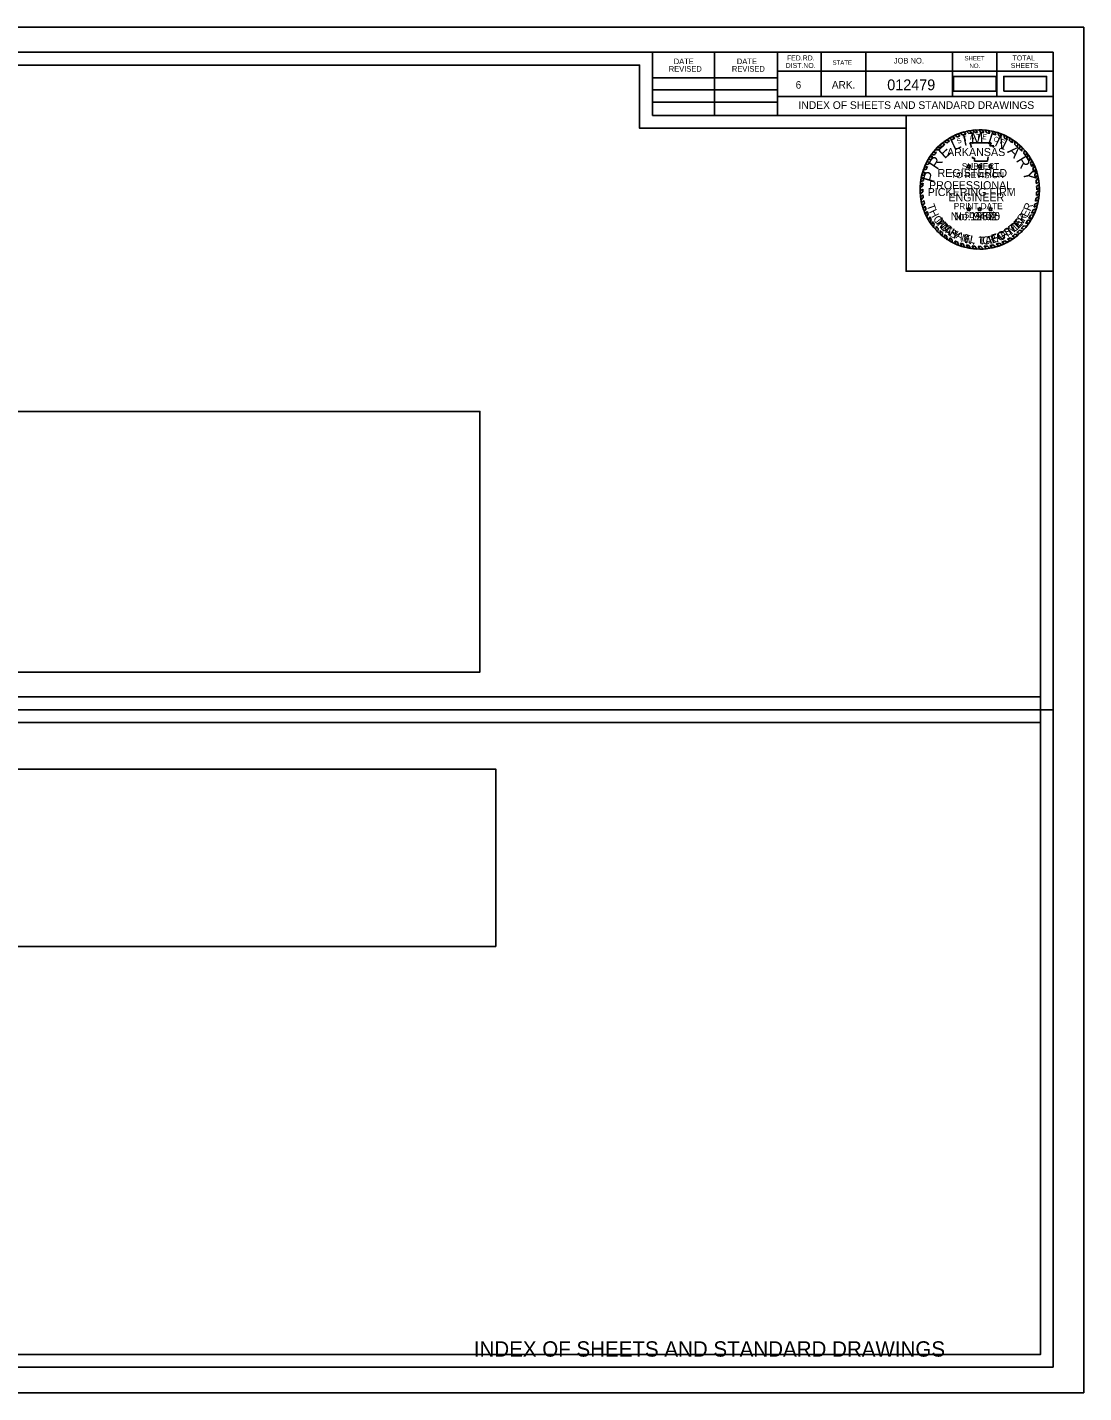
# Model space of a CAD drawing. Extents: x 1369290 to 1369980, y 379348 to 379562.
# Drawn here: x 1369458.1 to 1369623.1, y 379348.4 to 379561.7 of the extents above; entities that cross this region are included whole.
import ezdxf

# ---------------------------------------------------------------- set-up
doc = ezdxf.new("R2010")
doc.units = 0
for name, color, linetype in [('Default', 7, 'Continuous'), ('R_Border', 7, 'Continuous'), ('R_Border Notes', 7, 'Continuous'), ('R_Border Plan-Plan', 7, 'Continuous'), ('R_Border Title', 7, 'Continuous'), ('R_No Plot', 7, 'Continuous'), ('STAMP_PE_CRAFTON', 7, 'Continuous'), ('STAMP_PE_FOSTER', 7, 'Continuous'), ('STAMP_PE_SEAL-INFO', 7, 'Continuous'), ('STAMP_PE_TAEGTMEYER', 7, 'Continuous'), ('STAMP_PE_TXT', 7, 'Continuous'), ('STAMP_PRELIMINARY', 7, 'Continuous')]:
    doc.layers.add(name, color=color, linetype=linetype)

msp = doc.modelspace()

# ---------------------------------------------------------------- linework, layer by layer
at = {"layer": 'Default'}
for points in [[(1369602.79, 379551.74), (1369609.47, 379551.74), (1369609.47, 379554.05), (1369602.79, 379554.05)], [(1369610.66, 379551.74), (1369617.34, 379551.74), (1369617.34, 379554.05), (1369610.66, 379554.05)], [(1369384.17, 379460.99), (1369528.79, 379460.99), (1369528.79, 379501.71), (1369384.17, 379501.71)], [(1369381.68, 379418.12), (1369531.28, 379418.12), (1369531.28, 379445.83), (1369381.68, 379445.83)]]:
    msp.add_lwpolyline(points, close=True, dxfattribs=at)
at = {"layer": 'R_Border'}
for p, q in [((1369302.22, 379557.83), (1369618.4, 379557.83)), ((1369555.76, 379547.95), (1369555.76, 379557.83)), ((1369565.44, 379547.95), (1369565.44, 379557.83)), ((1369575.3, 379557.83), (1369575.3, 379547.95)), ((1369582.14, 379557.83), (1369582.14, 379550.89)), ((1369589.08, 379557.83), (1369589.08, 379550.89)), ((1369602.66, 379557.83), (1369602.66, 379550.89)), ((1369609.6, 379557.83), (1369609.6, 379550.89)), ((1369618.4, 379352.37), (1369618.4, 379557.83)), ((1369555.76, 379553.81), (1369575.3, 379553.81)), ((1369618.4, 379554.89), (1369575.3, 379554.89)), ((1369618.4, 379554.91), (1369618.4, 379554.91)), ((1369555.76, 379551.95), (1369575.3, 379551.95)), ((1369555.76, 379550.01), (1369575.3, 379550.01)), ((1369618.4, 379550.89), (1369575.3, 379550.89)), ((1369578.26, 379550.89), (1369618.4, 379550.89)), ((1369618.4, 379547.95), (1369555.76, 379547.95)), ((1369618.4, 379352.37), (1369302.22, 379352.37))]:
    msp.add_line(p, q, dxfattribs=at)
at = {"layer": 'R_Border Plan-Plan'}
msp.add_line((1369302.22, 379455.1), (1369618.4, 379455.1), dxfattribs=at)
at = {"layer": 'R_No Plot'}
for points in [[(1369289.81, 379561.73), (1369623.15, 379561.73), (1369623.15, 379348.39), (1369289.81, 379348.39)], [(1369616.4, 379457.1), (1369304.22, 379457.1), (1369304.22, 379555.83), (1369553.76, 379555.83), (1369553.76, 379545.95), (1369571.3, 379545.95), (1369595.4, 379545.95), (1369595.4, 379523.62), (1369616.4, 379523.62)], [(1369304.22, 379555.83), (1369553.76, 379555.83), (1369553.76, 379545.95), (1369571.3, 379545.95), (1369595.4, 379545.95), (1369595.4, 379523.62), (1369616.4, 379523.62), (1369616.4, 379354.37), (1369304.22, 379354.37)], [(1369595.4, 379547.95), (1369618.4, 379547.95), (1369618.4, 379523.62), (1369595.4, 379523.62)], [(1369304.22, 379453.1), (1369616.4, 379453.1), (1369616.4, 379354.37), (1369304.22, 379354.37)]]:
    msp.add_lwpolyline(points, close=True, dxfattribs=at)
at = {"layer": 'STAMP_PE_SEAL-INFO'}
for p, q in [((1369603, 379544.86), (1369603.39, 379544.59)), ((1369603.51, 379545.08), (1369603.8, 379544.75)), ((1369603.86, 379545.21), (1369604.24, 379544.9)), ((1369604.45, 379545.39), (1369604.74, 379545.04)), ((1369604.83, 379545.49), (1369605.19, 379545.14)), ((1369605.32, 379545.58), (1369605.62, 379545.22)), ((1369605.83, 379545.66), (1369606.11, 379545.27)), ((1369606.57, 379545.3), (1369606.26, 379545.7)), ((1369607.07, 379545.31), (1369606.79, 379545.72)), ((1369607.52, 379545.29), (1369607.27, 379545.71)), ((1369608.03, 379545.24), (1369607.74, 379545.68)), ((1369608.46, 379545.17), (1369608.2, 379545.63)), ((1369609.02, 379545.05), (1369608.84, 379545.51)), ((1369609.42, 379544.94), (1369609.26, 379545.41)), ((1369609.87, 379544.8), (1369609.73, 379545.28)), ((1369610.29, 379544.64), (1369610.15, 379545.13)), ((1369610.75, 379544.43), (1369610.65, 379544.93)), ((1369611.2, 379544.2), (1369611.11, 379544.71)), ((1369599.94, 379542.6), (1369600.46, 379542.56)), ((1369600.26, 379542.94), (1369600.8, 379542.9)), ((1369600.59, 379543.26), (1369601.05, 379543.12)), ((1369600.94, 379543.56), (1369601.47, 379543.46)), ((1369601.31, 379543.89), (1369601.77, 379543.69)), ((1369601.73, 379544.16), (1369602.18, 379543.96)), ((1369602.12, 379544.4), (1369602.55, 379544.18)), ((1369602.57, 379544.65), (1369603.03, 379544.43)), ((1369605.37, 379543.69), (1369608.71, 379543.69)), ((1369605.49, 379543.38), (1369605.37, 379543.69)), ((1369605.59, 379543.08), (1369605.49, 379543.38)), ((1369605.6, 379542.97), (1369605.59, 379543.08)), ((1369608.71, 379543.69), (1369608.49, 379543.19)), ((1369608.49, 379543.19), (1369609.12, 379543.19)), ((1369609.12, 379543.19), (1369608.98, 379542.97)), ((1369611.58, 379543.98), (1369611.54, 379544.48)), ((1369612.02, 379543.69), (1369611.99, 379544.2)), ((1369612.38, 379543.42), (1369612.41, 379543.91)), ((1369612.83, 379543.05), (1369612.85, 379543.57)), ((1369613.14, 379542.76), (1369613.21, 379543.26)), ((1369613.5, 379542.38), (1369613.56, 379542.91)), ((1369613.77, 379542.07), (1369613.91, 379542.54)), ((1369598.6, 379540.65), (1369599.1, 379540.71)), ((1369598.83, 379541.07), (1369599.32, 379541.09)), ((1369599.08, 379541.47), (1369599.59, 379541.5)), ((1369599.31, 379541.82), (1369599.82, 379541.81)), ((1369599.59, 379542.18), (1369600.14, 379542.21)), ((1369605.79, 379541.26), (1369605.77, 379541.48)), ((1369606.11, 379541.26), (1369605.79, 379541.26)), ((1369606.11, 379540.83), (1369606.11, 379541.26)), ((1369608.14, 379540.83), (1369606.11, 379540.83)), ((1369608.15, 379541.17), (1369608.14, 379540.83)), ((1369608.23, 379541.48), (1369608.15, 379541.17)), ((1369614.1, 379541.65), (1369614.23, 379542.15)), ((1369614.32, 379541.34), (1369614.49, 379541.8)), ((1369614.62, 379540.84), (1369614.81, 379541.33)), ((1369614.82, 379540.47), (1369615.05, 379540.92)), ((1369615.05, 379539.99), (1369615.28, 379540.47)), ((1369598.18, 379538.26), (1369597.72, 379538.01)), ((1369597.82, 379538.51), (1369598.29, 379538.7)), ((1369597.92, 379538.92), (1369598.4, 379539.08)), ((1369598.08, 379539.42), (1369598.56, 379539.56)), ((1369598.23, 379539.83), (1369598.73, 379539.97)), ((1369598.41, 379540.26), (1369598.91, 379540.36)), ((1369615.19, 379539.65), (1369615.46, 379540.08)), ((1369615.39, 379539.1), (1369615.66, 379539.58)), ((1369615.5, 379538.74), (1369615.79, 379539.19)), ((1369615.63, 379538.18), (1369615.95, 379538.63)), ((1369598, 379536.94), (1369597.58, 379536.69)), ((1369597.98, 379536.45), (1369597.58, 379536.11)), ((1369598.04, 379537.37), (1369597.6, 379537.09)), ((1369598.1, 379537.8), (1369597.65, 379537.58)), ((1369615.7, 379537.8), (1369616.05, 379538.15)), ((1369615.77, 379537.29), (1369616.14, 379537.63)), ((1369615.8, 379536.87), (1369616.19, 379537.16)), ((1369615.8, 379535.95), (1369616.22, 379536.22)), ((1369615.81, 379536.35), (1369616.22, 379536.67)), ((1369597.99, 379536.04), (1369597.6, 379535.72)), ((1369598.02, 379535.55), (1369597.65, 379535.19)), ((1369598.08, 379535.12), (1369597.72, 379534.74)), ((1369598.15, 379534.66), (1369597.81, 379534.29)), ((1369598.25, 379534.24), (1369597.94, 379533.83)), ((1369615.51, 379534.1), (1369615.98, 379534.3)), ((1369615.62, 379534.55), (1369616.07, 379534.75)), ((1369615.71, 379535.05), (1369616.15, 379535.27)), ((1369615.76, 379535.44), (1369616.19, 379535.7)), ((1369598.37, 379533.79), (1369598.08, 379533.38)), ((1369598.51, 379533.37), (1369598.23, 379532.96)), ((1369598.68, 379532.94), (1369598.42, 379532.52)), ((1369598.85, 379532.56), (1369598.62, 379532.1)), ((1369599.08, 379532.1), (1369598.89, 379531.61)), ((1369614.58, 379531.88), (1369615.08, 379531.93)), ((1369614.85, 379532.38), (1369615.34, 379532.44)), ((1369615.01, 379532.71), (1369615.5, 379532.81)), ((1369615.23, 379533.23), (1369615.71, 379533.36)), ((1369615.36, 379533.61), (1369615.85, 379533.81)), ((1369599.32, 379531.7), (1369599.14, 379531.23)), ((1369599.52, 379531.39), (1369599.41, 379530.83)), ((1369599.8, 379531), (1369599.7, 379530.47)), ((1369600.11, 379530.62), (1369600.02, 379530.1)), ((1369600.41, 379530.28), (1369600.35, 379529.76)), ((1369600.73, 379529.96), (1369600.7, 379529.43)), ((1369613.12, 379530.02), (1369613.56, 379529.88)), ((1369613.38, 379530.28), (1369613.86, 379530.19)), ((1369613.76, 379530.71), (1369614.22, 379530.63)), ((1369614.07, 379531.1), (1369614.57, 379531.11)), ((1369614.41, 379531.6), (1369614.89, 379531.59)), ((1369601.08, 379529.64), (1369601.07, 379529.11)), ((1369601.44, 379529.35), (1369601.46, 379528.82)), ((1369601.78, 379529.1), (1369601.81, 379528.58)), ((1369602.2, 379528.82), (1369602.26, 379528.3)), ((1369602.55, 379528.61), (1369602.64, 379528.1)), ((1369603.03, 379528.36), (1369603.19, 379527.84)), ((1369603.41, 379528.19), (1369603.58, 379527.68)), ((1369603.9, 379528), (1369604.11, 379527.5)), ((1369604.31, 379527.87), (1369604.53, 379527.38)), ((1369604.82, 379527.73), (1369605.03, 379527.26)), ((1369605.21, 379527.64), (1369605.46, 379527.18)), ((1369608.5, 379527.63), (1369608.89, 379527.29)), ((1369608.99, 379527.73), (1369609.37, 379527.41)), ((1369609.45, 379527.85), (1369609.87, 379527.56)), ((1369609.94, 379528.02), (1369610.39, 379527.75)), ((1369610.36, 379528.18), (1369610.78, 379527.92)), ((1369610.82, 379528.39), (1369611.3, 379528.18)), ((1369611.23, 379528.6), (1369611.65, 379528.37)), ((1369611.64, 379528.85), (1369612.09, 379528.65)), ((1369611.99, 379529.08), (1369612.43, 379528.89)), ((1369612.45, 379529.42), (1369612.92, 379529.27)), ((1369612.72, 379529.64), (1369613.19, 379529.52)), ((1369605.71, 379527.56), (1369605.95, 379527.12)), ((1369606.15, 379527.51), (1369606.43, 379527.08)), ((1369606.64, 379527.48), (1369606.94, 379527.07)), ((1369607.1, 379527.48), (1369607.44, 379527.09)), ((1369607.61, 379527.51), (1369607.94, 379527.13)), ((1369608.05, 379527.56), (1369608.43, 379527.2))]:
    msp.add_line(p, q, dxfattribs=at)
for radius, start, end in [(9.32, 111.3124, 114.7026), (8.91, 110.3086, 113.1659), (9.32, 105.2339, 109.0352), (8.91, 104.0352, 107.3615), (9.32, 99.7525, 102.7765), (8.91, 98.258, 101.0329), (9.32, 93.9381, 96.5517), (8.91, 92.1102, 95.0367), (9.32, 87.7298, 90.6707), (8.91, 85.9628, 88.9097), (9.32, 81.9732, 84.8236), (8.91, 79.9264, 82.696), (9.32, 75.3125, 77.9426), (8.91, 73.5575, 76.2314), (9.32, 69.6061, 72.3058), (8.91, 67.6248, 70.504), (9.32, 63.1329, 66.2704), (9.32, 135.4021, 138.3031), (8.91, 133.1331, 136.2562), (9.32, 129.7326, 132.5376), (8.91, 127.5297, 130.9683), (9.32, 123.6199, 126.5906), (8.91, 121.9746, 125.11), (9.32, 117.6544, 120.8099), (8.91, 115.6869, 119.1583), (8.91, 61.1558, 64.3784), (9.32, 56.9003, 60.0942), (8.91, 54.9238, 58.2702), (8.91, 48.3016, 52.0395), (9.32, 50.3492, 53.7159), (8.91, 42.2212, 45.5512), (9.32, 44.3405, 47.3929), (9.32, 38.1247, 41.2316), (9.32, 152.864, 155.5189), (9.32, 147.0072, 149.899), (8.91, 151.0315, 153.573), (9.32, 141.6056, 144.4486), (8.91, 145.0197, 148.2104), (8.91, 139.301, 142.5873), (8.91, 36.135, 39.5311), (8.91, 29.9032, 33.6645), (9.32, 31.9614, 35.4294), (8.91, 23.7732, 27.2211), (9.32, 25.9391, 29.0125), (9.32, 164.3068, 166.894), (9.32, 158.4077, 161.0701), (8.91, 167.9048, 170.9039), (8.91, 162.4331, 165.0013), (8.91, 156.3402, 159.2319), (8.91, 17.6802, 21.4251), (9.32, 19.9538, 23.3141), (8.91, 11.5444, 15.2364), (9.32, 13.8421, 17.4447), (9.32, 175.7409, 178.2066), (9.32, 170.0003, 172.6878), (8.91, 179.6454, 182.2633), (8.91, 173.73, 176.4734), (8.91, 5.7599, 9.0606), (8.91, 359.7329, 3.0639), (9.32, 7.5852, 10.8621), (9.32, 1.7215, 4.7268), (9.32, 355.7156, 358.9569), (9.32, 181.7251, 184.1626), (9.32, 187.4204, 190.1927), (9.32, 193.0369, 195.9973), (8.91, 185.4539, 188.234), (8.91, 191.2274, 193.9858), (8.91, 341.777, 345.0925), (8.91, 348.0778, 351.3435), (8.91, 353.8632, 357.1274), (9.32, 343.8925, 347.035), (9.32, 349.8305, 353.0885), (9.32, 198.8967, 201.6281), (8.91, 196.9675, 199.8353), (9.32, 204.5479, 207.4328), (8.91, 202.7761, 205.4791), (8.91, 208.7883, 211.7934), (8.91, 329.5549, 333.2076), (8.91, 335.6038, 339.1858), (9.32, 331.4037, 334.9332), (9.32, 337.3837, 340.9933), (9.32, 210.8636, 213.6571), (9.32, 216.6115, 219.491), (8.91, 214.1838, 217.2747), (9.32, 222.48, 225.3801), (8.91, 220.3909, 223.3056), (8.91, 226.2494, 229.2407), (8.91, 310.7744, 314.3161), (9.32, 312.4518, 315.6633), (8.91, 316.6531, 320.3711), (9.32, 318.2846, 321.8043), (8.91, 323.5851, 327.4407), (9.32, 325.4405, 328.9872), (9.32, 228.3665, 231.348), (8.91, 232.229, 234.9336), (9.32, 234.295, 236.9452), (8.91, 238.2223, 240.8353), (9.32, 240.1977, 242.8613), (8.91, 244.3204, 246.9486), (9.32, 246.576, 249.1558), (8.91, 250.3491, 253.1216), (8.91, 256.505, 259.1192), (8.91, 280.3459, 283.5814), (8.91, 286.6423, 289.9783), (9.32, 288.5709, 291.9733), (8.91, 292.8745, 296.1185), (9.32, 294.6481, 298.2166), (8.91, 299.0768, 302.1724), (9.32, 300.621, 303.8703), (8.91, 304.823, 308.5143), (9.32, 306.3721, 310.208), (9.32, 252.5967, 255.3252), (9.32, 258.4433, 261.1398), (8.91, 262.3783, 265.2012), (9.32, 264.1978, 267.1009), (8.91, 268.3215, 271.277), (9.32, 270.2548, 273.3361), (8.91, 274.6157, 277.4486), (9.32, 276.4239, 279.4357), (9.32, 282.3199, 285.3702)]:
    msp.add_arc((1369606.9, 379536.39), radius, start, end, dxfattribs=at)
at = {"layer": 'STAMP_PE_TXT'}
for p, q in [((1369605.08, 379539.97), (1369604.88, 379540.11)), ((1369604.88, 379540.11), (1369605.12, 379540.11)), ((1369605, 379539.73), (1369605.08, 379539.97)), ((1369605.2, 379539.88), (1369605, 379539.73)), ((1369605.12, 379540.11), (1369605.2, 379540.34)), ((1369605.2, 379540.34), (1369605.27, 379540.11)), ((1369605.4, 379539.73), (1369605.2, 379539.88)), ((1369605.27, 379540.11), (1369605.52, 379540.11)), ((1369605.52, 379540.11), (1369605.32, 379539.97)), ((1369605.32, 379539.97), (1369605.4, 379539.73)), ((1369606.77, 379539.97), (1369606.58, 379540.11)), ((1369606.58, 379540.11), (1369606.82, 379540.11)), ((1369606.7, 379539.73), (1369606.77, 379539.97)), ((1369606.9, 379539.88), (1369606.7, 379539.73)), ((1369606.82, 379540.11), (1369606.9, 379540.34)), ((1369606.9, 379540.34), (1369606.97, 379540.11)), ((1369607.1, 379539.73), (1369606.9, 379539.88)), ((1369606.97, 379540.11), (1369607.22, 379540.11)), ((1369607.22, 379540.11), (1369607.02, 379539.97)), ((1369607.02, 379539.97), (1369607.1, 379539.73)), ((1369608.47, 379539.97), (1369608.27, 379540.11)), ((1369608.27, 379540.11), (1369608.52, 379540.11)), ((1369608.4, 379539.73), (1369608.47, 379539.97)), ((1369608.59, 379539.88), (1369608.4, 379539.73)), ((1369608.52, 379540.11), (1369608.59, 379540.34)), ((1369608.59, 379540.34), (1369608.67, 379540.11)), ((1369608.79, 379539.73), (1369608.59, 379539.88)), ((1369608.67, 379540.11), (1369608.92, 379540.11)), ((1369608.92, 379540.11), (1369608.72, 379539.97)), ((1369608.72, 379539.97), (1369608.79, 379539.73)), ((1369605.08, 379533.26), (1369604.88, 379533.4)), ((1369604.88, 379533.4), (1369605.12, 379533.4)), ((1369605, 379533.03), (1369605.08, 379533.26)), ((1369605.2, 379533.17), (1369605, 379533.03)), ((1369605.12, 379533.4), (1369605.2, 379533.64)), ((1369605.2, 379533.64), (1369605.27, 379533.4)), ((1369605.4, 379533.03), (1369605.2, 379533.17)), ((1369605.27, 379533.4), (1369605.52, 379533.4)), ((1369605.52, 379533.4), (1369605.32, 379533.26)), ((1369605.32, 379533.26), (1369605.4, 379533.03)), ((1369606.77, 379533.26), (1369606.58, 379533.4)), ((1369606.58, 379533.4), (1369606.82, 379533.4)), ((1369606.7, 379533.03), (1369606.77, 379533.26)), ((1369606.9, 379533.17), (1369606.7, 379533.03)), ((1369606.82, 379533.4), (1369606.9, 379533.64)), ((1369606.9, 379533.64), (1369606.97, 379533.4)), ((1369607.1, 379533.03), (1369606.9, 379533.17)), ((1369606.97, 379533.4), (1369607.22, 379533.4)), ((1369607.22, 379533.4), (1369607.02, 379533.26)), ((1369607.02, 379533.26), (1369607.1, 379533.03)), ((1369608.47, 379533.26), (1369608.27, 379533.4)), ((1369608.27, 379533.4), (1369608.52, 379533.4)), ((1369608.4, 379533.03), (1369608.47, 379533.26)), ((1369608.59, 379533.17), (1369608.4, 379533.03)), ((1369608.52, 379533.4), (1369608.59, 379533.64)), ((1369608.59, 379533.64), (1369608.67, 379533.4)), ((1369608.79, 379533.03), (1369608.59, 379533.17)), ((1369608.67, 379533.4), (1369608.92, 379533.4)), ((1369608.92, 379533.4), (1369608.72, 379533.26)), ((1369608.72, 379533.26), (1369608.79, 379533.03))]:
    msp.add_line(p, q, dxfattribs=at)
at = {"layer": 'STAMP_PRELIMINARY'}
msp.add_circle((1369606.9, 379536.39), 9.32, dxfattribs=at)

# ---------------------------------------------------------------- texts
at = {"layer": 'R_Border'}
for s, height, p in [('REVISED', 0.879, (1369558.31, 379554.79)), ('DATE', 0.879, (1369559.09, 379555.97)), ('REVISED', 0.879, (1369568.17, 379554.79)), ('DATE', 0.879, (1369568.95, 379555.97)), ('DIST.NO.', 0.782, (1369576.58, 379555.37)), ('FED.RD.', 0.782, (1369576.78, 379556.55)), ('STATE', 0.684, (1369583.9, 379555.87)), ('JOB NO.', 0.879, (1369593.48, 379556.07)), ('SHEET', 0.684, (1369604.52, 379556.55)), ('NO.', 0.684, (1369605.3, 379555.37)), ('SHEETS', 0.782, (1369611.76, 379555.37)), ('TOTAL', 0.782, (1369612.04, 379556.55)), ('6', 1.17, (1369578.14, 379552.15)), ('ARK.', 1.172, (1369583.8, 379552.15))]:
    msp.add_text(s, height=height, dxfattribs=at).set_placement(p)
at = {"layer": 'R_Border Notes'}
for s, height, p in [('012479', 1.68, (1369592.45, 379551.9)), ('INDEX OF SHEETS AND STANDARD DRAWINGS', 1.2, (1369578.59, 379548.97))]:
    msp.add_text(s, height=height, dxfattribs=at).set_placement(p)
at = {"layer": 'R_Border Title'}
msp.add_text('INDEX OF SHEETS AND STANDARD DRAWINGS', height=2.4, dxfattribs=at).set_placement((1369527.84, 379354.02))
at = {"layer": 'STAMP_PE_CRAFTON'}
for s, rotation, p in [('T', 310.7442, (1369599.86, 379531.29)), ('N', 49.2411, (1369613.18, 379530.42)), ('O', 317.6422, (1369600.53, 379530.48)), ('N', 324.4537, (1369601.38, 379529.7)), ('Y', 331.1686, (1369602.41, 379528.98)), ('F', 28.7821, (1369610.56, 379528.52)), ('T', 34.1136, (1369611.47, 379529.03)), ('O', 41.8391, (1369612.33, 379529.64)), ('N', 347.4752, (1369604.46, 379528.06)), ('.', 356.8926, (1369605.69, 379527.79)), ('C', 6.0117, (1369607.37, 379527.74)), ('R', 14.8189, (1369608.46, 379527.85)), ('A', 20.5125, (1369609.58, 379528.15))]:
    msp.add_text(s, height=1.25, rotation=rotation, dxfattribs=at).set_placement(p)
msp.add_text('No. 12370', height=1.25, dxfattribs=at).set_placement((1369602.36, 379531.59))
at = {"layer": 'STAMP_PE_FOSTER'}
for s, rotation, p in [('M', 308.339, (1369600.01, 379531.42)), ('E', 46.9613, (1369612.9, 379530.38)), ('R', 54.5031, (1369613.62, 379531.21)), ('I', 314.1842, (1369600.81, 379530.48)), ('C', 319.8733, (1369601.16, 379530.13)), ('H', 327.7235, (1369602.09, 379529.39)), ('O', 23.719, (1369609.98, 379528.48)), ('S', 31.7234, (1369611.09, 379529.01)), ('T', 39.4194, (1369612.04, 379529.63)), ('A', 335.7276, (1369603.07, 379528.81)), ('E', 343.5779, (1369604.21, 379528.34)), ('L', 350.8115, (1369605.27, 379528.06)), ('L', 1.2666, (1369606.81, 379527.9)), ('.', 6.8035, (1369607.86, 379527.96)), ('F', 15.8691, (1369608.93, 379528.15))]:
    msp.add_text(s, height=1.2, rotation=rotation, dxfattribs=at).set_placement(p)
msp.add_text('No. 9402', height=1.25, dxfattribs=at).set_placement((1369602.88, 379531.59))
at = {"layer": 'STAMP_PE_TAEGTMEYER'}
for s, rotation, p in [('T', 289.646, (1369598.59, 379533.9)), ('R', 69.57, (1369614.84, 379532.91)), ('H', 296.7339, (1369598.95, 379532.92)), ('O', 303.7708, (1369599.54, 379531.81)), ('Y', 53.9986, (1369613.67, 379530.99)), ('E', 63.0984, (1369614.34, 379531.93)), ('M', 314.2033, (1369600.2, 379530.86)), ('A', 321.0594, (1369601.16, 379529.9)), ('S', 327.8239, (1369601.99, 379529.25)), ('G', 23.3052, (1369609.9, 379528.26)), ('T', 31.466, (1369611, 379528.75)), ('M', 39.3, (1369611.89, 379529.29)), ('E', 46.8094, (1369612.94, 379530.17)), ('N', 344.2727, (1369603.88, 379528.25)), ('.', 350.6464, (1369605.1, 379527.91)), ('T', 3.0061, (1369606.76, 379527.72)), ('A', 8.9826, (1369607.81, 379527.77)), ('E', 17.6836, (1369608.85, 379527.93))]:
    msp.add_text(s, height=1.25, rotation=rotation, dxfattribs=at).set_placement(p)
msp.add_text('No. 19605', height=1.25, dxfattribs=at).set_placement((1369602.36, 379531.59))
at = {"layer": 'STAMP_PE_TXT'}
for s, rotation, p in [('T', 16.311, (1369604.42, 379543.87)), ('A', 9.0679, (1369605.38, 379544.12)), ('T', 1.8248, (1369606.37, 379544.25)), ('E', 355.2002, (1369607.28, 379544.26)), ('O', 342.2506, (1369609, 379543.98)), ('S', 23.5541, (1369603.5, 379543.5)), ('F', 335.0075, (1369609.97, 379543.65))]:
    msp.add_text(s, height=0.781, rotation=rotation, dxfattribs=at).set_placement(p)
for s, p in [('ARKANSAS', (1369601.79, 379541.61)), ('REGISTERED', (1369600.31, 379538.34)), ('PROFESSIONAL', (1369598.97, 379536.43)), ('ENGINEER', (1369602.01, 379534.53))]:
    msp.add_text(s, height=1.25, dxfattribs=at).set_placement(p)
at = {"layer": 'STAMP_PRELIMINARY'}
for s, rotation, p in [('I', 12.5248, (1369604.43, 379543.18)), ('M', 3.1074, (1369605.53, 379543.49)), ('I', 342.3164, (1369608, 379543.56)), ('N', 333.9382, (1369609.11, 379543.28)), ('E', 42.3578, (1369601.42, 379541.09)), ('L', 25.513, (1369602.91, 379542.42)), ('A', 315.6579, (1369611.14, 379542.26)), ('R', 56.2292, (1369600.27, 379539.36)), ('R', 301.3831, (1369612.51, 379540.94)), ('P', 73.913, (1369599.72, 379537.34)), ('Y', 283.2593, (1369613.6, 379539.16))]:
    msp.add_text(s, height=1.8, rotation=rotation, dxfattribs=at).set_placement(p)
for s, height, p in [('SUBJECT', 0.96, (1369604.1, 379539.54)), ('TO REVISION', 0.96, (1369602.43, 379538.16)), ('PICKERING FIRM', 1.25, (1369598.77, 379535.36)), ('PRINT DATE', 0.96, (1369602.85, 379533.31)), ('$DATE$', 0.96, (1369604.53, 379531.93))]:
    msp.add_text(s, height=height, dxfattribs=at).set_placement(p)

doc.saveas('drawing.dxf')
